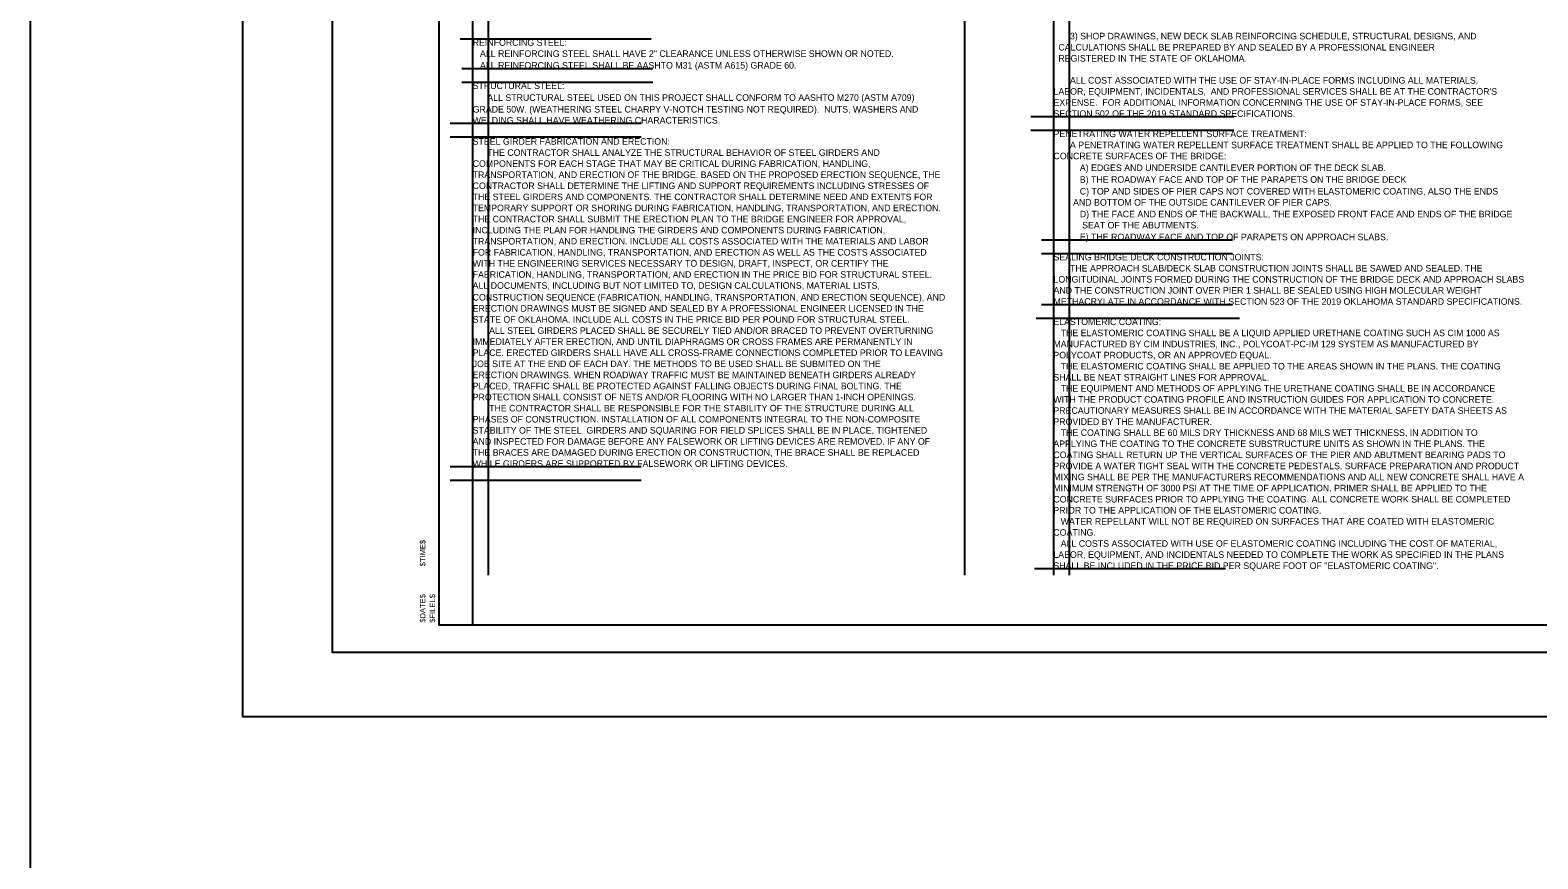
# Model space of a CAD drawing. Extents: x 12303.1 to 12355.9, y 579 to 640.5.
# Drawn here: x 12312.48 to 12340.01, y 610.44 to 625.59 of the extents above; entities that cross this region are included whole.
import ezdxf

# ---------------------------------------------------------------- set-up
doc = ezdxf.new("R2010")
doc.units = 0
for name, color, linetype in [('S', 7, 'Continuous'), ('SHT_Plot_Shape_Full', 7, 'Continuous'), ('SHT_Plot_Shape_Half', 7, 'Continuous'), ('SHT_Plot_Stamp', 7, 'Continuous'), ('SHT_Sheet_Border', 7, 'Continuous'), ('T', 7, 'Continuous')]:
    doc.layers.add(name, color=color, linetype=linetype)

# ---------------------------------------------------------------- blocks, each defined once
blk = doc.blocks.new('Stamp_Plot_Stamp')
at = {"layer": 'SHT_Plot_Stamp'}
for s, p in [('$TIME$', (8.01, 7.43)), ('$DATE$', (8.01, 2.56)), ('$FILEL$', (8.85, 2.56))]:
    blk.add_text(s, height=0.472, rotation=90, dxfattribs=at).set_placement(p)

msp = doc.modelspace()

# ---------------------------------------------------------------- linework, layer by layer
at = {"layer": 'Defpoints'}
for p, q in [((12320.557, 635.276), (12320.557, 614.717)), ((12320.841, 635.276), (12320.841, 615.626)), ((12329.542, 635.276), (12329.542, 615.626)), ((12331.165, 635.276), (12331.165, 615.626)), ((12331.45, 635.276), (12331.45, 615.626)), ((12323.819, 625.422), (12320.33, 625.422)), ((12323.847, 624.884), (12320.358, 624.884)), ((12323.847, 624.634), (12320.358, 624.634)), ((12334.242, 624.003), (12330.752, 624.003)), ((12334.458, 624.003), (12330.969, 624.003)), ((12323.633, 623.881), (12320.144, 623.881)), ((12334.242, 623.753), (12330.752, 623.753)), ((12334.458, 623.753), (12330.969, 623.753)), ((12323.633, 623.631), (12320.144, 623.631)), ((12334.436, 621.749), (12330.946, 621.749)), ((12334.436, 621.499), (12330.946, 621.499)), ((12334.436, 620.569), (12330.946, 620.569)), ((12334.34, 620.319), (12330.85, 620.319)), ((12334.436, 620.319), (12330.946, 620.319)), ((12334.562, 620.319), (12331.072, 620.319)), ((12323.633, 617.607), (12320.144, 617.607)), ((12323.633, 617.357), (12320.144, 617.357)), ((12334.307, 615.741), (12330.817, 615.741))]:
    msp.add_line(p, q, dxfattribs=at)
at = {"layer": 'S'}
msp.add_lwpolyline([(12355.912, 640.488), (12312.476, 640.488), (12312.476, 579.031), (12355.912, 579.031)], close=True, dxfattribs=at)
at = {"layer": 'SHT_Plot_Shape_Full'}
msp.add_lwpolyline([(12316.36, 637.042), (12352.36, 637.042), (12352.36, 613.042), (12316.36, 613.042)], close=True, dxfattribs=at)
at = {"layer": 'SHT_Plot_Shape_Half'}
msp.add_lwpolyline([(12317.998, 636.217), (12351.998, 636.217), (12351.998, 614.217), (12317.998, 614.217)], close=True, dxfattribs=at)
at = {"layer": 'SHT_Sheet_Border'}
msp.add_lwpolyline([(12351.448, 614.717), (12319.948, 614.717), (12319.948, 635.717), (12351.448, 635.717)], close=True, dxfattribs=at)

# ---------------------------------------------------------------- block references
at = {"layer": 'SHT_Plot_Stamp', "xscale": 0.21166666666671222, "yscale": 0.21166666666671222}
msp.add_blockref('Stamp_Plot_Stamp', (12317.998, 614.217), dxfattribs=at)

# ---------------------------------------------------------------- texts
at = {"layer": 'T'}
for s, p in [('REINFORCING STEEL:', (12320.557, 625.302)), ('  CALCULATIONS SHALL BE PREPARED BY AND SEALED BY A PROFESSIONAL ENGINEER', (12331.165, 625.216)), ('3) SHOP DRAWINGS, NEW DECK SLAB REINFORCING SCHEDULE, STRUCTURAL DESIGNS, AND', (12331.465, 625.419)), ('   ALL REINFORCING STEEL SHALL HAVE 2" CLEARANCE UNLESS OTHERWISE SHOWN OR NOTED.', (12320.557, 625.099)), ('  REGISTERED IN THE STATE OF OKLAHOMA.', (12331.165, 625.013)), ('   ALL REINFORCING STEEL SHALL BE AASHTO M31 (ASTM A615) GRADE 60.', (12320.557, 624.885)), ('STRUCTURAL STEEL:', (12320.557, 624.511)), ("LABOR, EQUIPMENT, INCIDENTALS,  AND PROFESSIONAL SERVICES SHALL BE AT THE CONTRACTOR'S ", (12331.165, 624.408)), ('ALL COST ASSOCIATED WITH THE USE OF STAY-IN-PLACE FORMS INCLUDING ALL MATERIALS, ', (12331.465, 624.611)), ('GRADE 50W. (WEATHERING STEEL CHARPY V-NOTCH TESTING NOT REQUIRED).  NUTS, WASHERS AND ', (12320.557, 624.082)), ('      ALL STRUCTURAL STEEL USED ON THIS PROJECT SHALL CONFORM TO AASHTO M270 (ASTM A709) ', (12320.557, 624.296)), ('EXPENSE.  FOR ADDITIONAL INFORMATION CONCERNING THE USE OF STAY-IN-PLACE FORMS, SEE ', (12331.165, 624.206)), ('WELDING SHALL HAVE WEATHERING CHARACTERISTICS.', (12320.557, 623.881)), ('SECTION 502 OF THE 2019 STANDARD SPECIFICATIONS.', (12331.165, 624.003)), ('PENETRATING WATER REPELLENT SURFACE TREATMENT:', (12331.165, 623.633)), ('STEEL GIRDER FABRICATION AND ERECTION:', (12320.557, 623.494)), ('      THE CONTRACTOR SHALL ANALYZE THE STRUCTURAL BEHAVIOR OF STEEL GIRDERS AND ', (12320.557, 623.291)), ('A PENETRATING WATER REPELLENT SURFACE TREATMENT SHALL BE APPLIED TO THE FOLLOWING ', (12331.465, 623.431)), ('COMPONENTS FOR EACH STAGE THAT MAY BE CRITICAL DURING FABRICATION, HANDLING, ', (12320.557, 623.089)), ('CONCRETE SURFACES OF THE BRIDGE:', (12331.165, 623.228)), ('A) EDGES AND UNDERSIDE CANTILEVER PORTION OF THE DECK SLAB.', (12331.645, 623.013)), ('TRANSPORTATION, AND ERECTION OF THE BRIDGE. BASED ON THE PROPOSED ERECTION SEQUENCE, THE ', (12320.557, 622.886)), ('B) THE ROADWAY FACE AND TOP OF THE PARAPETS ON THE BRIDGE DECK', (12331.645, 622.799)), ('THE STEEL GIRDERS AND COMPONENTS. THE CONTRACTOR SHALL DETERMINE NEED AND EXTENTS FOR ', (12320.557, 622.481)), ('CONTRACTOR SHALL DETERMINE THE LIFTING AND SUPPORT REQUIREMENTS INCLUDING STRESSES OF ', (12320.557, 622.684)), ('C) TOP AND SIDES OF PIER CAPS NOT COVERED WITH ELASTOMERIC COATING, ALSO THE ENDS ', (12331.645, 622.584)), ('TEMPORARY SUPPORT OR SHORING DURING FABRICATION, HANDLING, TRANSPORTATION, AND ERECTION. ', (12320.557, 622.279)), ('        AND BOTTOM OF THE OUTSIDE CANTILEVER OF PIER CAPS.', (12331.165, 622.381)), ('D) THE FACE AND ENDS OF THE BACKWALL, THE EXPOSED FRONT FACE AND ENDS OF THE BRIDGE    ', (12331.645, 622.167)), ('THE CONTRACTOR SHALL SUBMIT THE ERECTION PLAN TO THE BRIDGE ENGINEER FOR APPROVAL, ', (12320.557, 622.076)), ('INCLUDING THE PLAN FOR HANDLING THE GIRDERS AND COMPONENTS DURING FABRICATION, ', (12320.557, 621.873)), ('     SEAT OF THE ABUTMENTS.', (12331.465, 621.964)), ('TRANSPORTATION, AND ERECTION. INCLUDE ALL COSTS ASSOCIATED WITH THE MATERIALS AND LABOR ', (12320.557, 621.671)), ('E) THE ROADWAY FACE AND TOP OF PARAPETS ON APPROACH SLABS.', (12331.645, 621.749)), ('FOR FABRICATION, HANDLING, TRANSPORTATION, AND ERECTION AS WELL AS THE COSTS ASSOCIATED ', (12320.557, 621.468)), ('SEALING BRIDGE DECK CONSTRUCTION JOINTS:', (12331.165, 621.38)), ('WITH THE ENGINEERING SERVICES NECESSARY TO DESIGN, DRAFT, INSPECT, OR CERTIFY THE ', (12320.557, 621.266)), ('FABRICATION, HANDLING, TRANSPORTATION, AND ERECTION IN THE PRICE BID FOR STRUCTURAL STEEL. ', (12320.557, 621.063)), ('THE APPROACH SLAB/DECK SLAB CONSTRUCTION JOINTS SHALL BE SAWED AND SEALED. THE ', (12331.465, 621.177)), ('ALL DOCUMENTS, INCLUDING BUT NOT LIMITED TO, DESIGN CALCULATIONS, MATERIAL LISTS, ', (12320.557, 620.861)), ('AND THE CONSTRUCTION JOINT OVER PIER 1 SHALL BE SEALED USING HIGH MOLECULAR WEIGHT ', (12331.165, 620.772)), ('LONGITUDINAL JOINTS FORMED DURING THE CONSTRUCTION OF THE BRIDGE DECK AND APPROACH SLABS ', (12331.165, 620.975)), ('CONSTRUCTION SEQUENCE (FABRICATION, HANDLING, TRANSPORTATION, AND ERECTION SEQUENCE), AND ', (12320.557, 620.646)), ('METHACRYLATE IN ACCORDANCE WITH SECTION 523 OF THE 2019 OKLAHOMA STANDARD SPECIFICATIONS.', (12331.165, 620.569)), ('STATE OF OKLAHOMA. INCLUDE ALL COSTS IN THE PRICE BID PER POUND FOR STRUCTURAL STEEL.', (12320.557, 620.241)), ('ERECTION DRAWINGS MUST BE SIGNED AND SEALED BY A PROFESSIONAL ENGINEER LICENSED IN THE ', (12320.557, 620.443)), ('ALL STEEL GIRDERS PLACED SHALL BE SECURELY TIED AND/OR BRACED TO PREVENT OVERTURNING ', (12320.857, 620.038)), ('ELASTOMERIC COATING:', (12331.162, 620.198)), ('   THE ELASTOMERIC COATING SHALL BE A LIQUID APPLIED URETHANE COATING SUCH AS CIM 1000 AS ', (12331.162, 619.995)), ('IMMEDIATELY AFTER ERECTION, AND UNTIL DIAPHRAGMS OR CROSS FRAMES ARE PERMANENTLY IN ', (12320.557, 619.836)), ('MANUFACTURED BY CIM INDUSTRIES, INC., POLYCOAT-PC-IM 129 SYSTEM AS MANUFACTURED BY ', (12331.162, 619.792)), ('JOB SITE AT THE END OF EACH DAY. THE METHODS TO BE USED SHALL BE SUBMITED ON THE ', (12320.557, 619.43)), ('PLACE. ERECTED GIRDERS SHALL HAVE ALL CROSS-FRAME CONNECTIONS COMPLETED PRIOR TO LEAVING ', (12320.557, 619.633)), ('POLYCOAT PRODUCTS, OR AN APPROVED EQUAL.', (12331.162, 619.59)), ('ERECTION DRAWINGS. WHEN ROADWAY TRAFFIC MUST BE MAINTAINED BENEATH GIRDERS ALREADY ', (12320.557, 619.228)), ('SHALL BE NEAT STRAIGHT LINES FOR APPROVAL.', (12331.162, 619.185)), ('   THE ELASTOMERIC COATING SHALL BE APPLIED TO THE AREAS SHOWN IN THE PLANS. THE COATING ', (12331.162, 619.387)), ('PLACED, TRAFFIC SHALL BE PROTECTED AGAINST FALLING OBJECTS DURING FINAL BOLTING. THE ', (12320.557, 619.025)), ('   THE EQUIPMENT AND METHODS OF APPLYING THE URETHANE COATING SHALL BE IN ACCORDANCE ', (12331.162, 618.982)), ('PROTECTION SHALL CONSIST OF NETS AND/OR FLOORING WITH NO LARGER THAN 1-INCH OPENINGS. ', (12320.557, 618.823)), ('THE CONTRACTOR SHALL BE RESPONSIBLE FOR THE STABILITY OF THE STRUCTURE DURING ALL ', (12320.857, 618.62)), ('WITH THE PRODUCT COATING PROFILE AND INSTRUCTION GUIDES FOR APPLICATION TO CONCRETE. ', (12331.162, 618.78)), ('PRECAUTIONARY MEASURES SHALL BE IN ACCORDANCE WITH THE MATERIAL SAFETY DATA SHEETS AS ', (12331.162, 618.577)), ('PHASES OF CONSTRUCTION. INSTALLATION OF ALL COMPONENTS INTEGRAL TO THE NON-COMPOSITE ', (12320.557, 618.418)), ('PROVIDED BY THE MANUFACTURER.', (12331.162, 618.374)), ('STABILITY OF THE STEEL  GIRDERS AND SQUARING FOR FIELD SPLICES SHALL BE IN PLACE, TIGHTENED ', (12320.557, 618.215)), ('   THE COATING SHALL BE 60 MILS DRY THICKNESS AND 68 MILS WET THICKNESS, IN ADDITION TO ', (12331.162, 618.172)), ('AND INSPECTED FOR DAMAGE BEFORE ANY FALSEWORK OR LIFTING DEVICES ARE REMOVED. IF ANY OF ', (12320.557, 618.012)), ('THE BRACES ARE DAMAGED DURING ERECTION OR CONSTRUCTION, THE BRACE SHALL BE REPLACED ', (12320.557, 617.81)), ('APPLYING THE COATING TO THE CONCRETE SUBSTRUCTURE UNITS AS SHOWN IN THE PLANS. THE ', (12331.162, 617.969)), ('COATING SHALL RETURN UP THE VERTICAL SURFACES OF THE PIER AND ABUTMENT BEARING PADS TO ', (12331.162, 617.767)), ('WHILE GIRDERS ARE SUPPORTED BY FALSEWORK OR LIFTING DEVICES.', (12320.557, 617.607)), ('PROVIDE A WATER TIGHT SEAL WITH THE CONCRETE PEDESTALS. SURFACE PREPARATION AND PRODUCT ', (12331.162, 617.564)), ('MIXING SHALL BE PER THE MANUFACTURERS RECOMMENDATIONS AND ALL NEW CONCRETE SHALL HAVE A ', (12331.162, 617.362)), ('CONCRETE SURFACES PRIOR TO APPLYING THE COATING. ALL CONCRETE WORK SHALL BE COMPLETED ', (12331.162, 616.956)), ('MINIMUM STRENGTH OF 3000 PSI AT THE TIME OF APPLICATION. PRIMER SHALL BE APPLIED TO THE ', (12331.162, 617.159)), ('PRIOR TO THE APPLICATION OF THE ELASTOMERIC COATING.', (12331.162, 616.754)), ('   WATER REPELLANT WILL NOT BE REQUIRED ON SURFACES THAT ARE COATED WITH ELASTOMERIC ', (12331.162, 616.551)), ('COATING.', (12331.162, 616.349)), ('   ALL COSTS ASSOCIATED WITH USE OF ELASTOMERIC COATING INCLUDING THE COST OF MATERIAL, ', (12331.162, 616.146)), ('LABOR, EQUIPMENT, AND INCIDENTALS NEEDED TO COMPLETE THE WORK AS SPECIFIED IN THE PLANS ', (12331.162, 615.944)), ('SHALL BE INCLUDED IN THE PRICE BID PER SQUARE FOOT OF "ELASTOMERIC COATING".', (12331.162, 615.741))]:
    msp.add_text(s, height=0.12, dxfattribs=at).set_placement(p)

doc.saveas('drawing.dxf')
